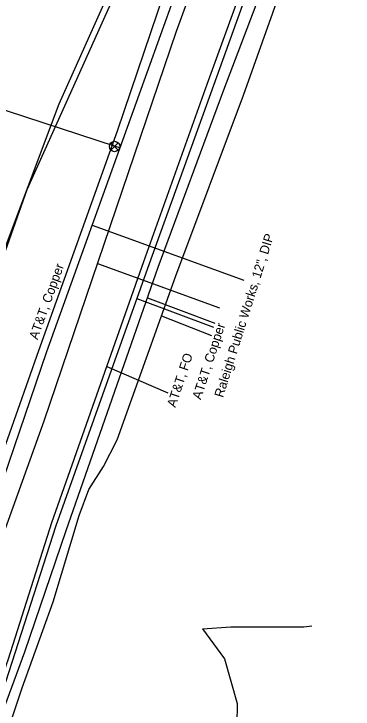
# Model space of a CAD drawing. Extents: x 2070721 to 2083039, y 729290 to 737883.
# Drawn here: x 2081041.1 to 2081187.2, y 732953.4 to 733253 of the extents above; entities that cross this region are included whole.
import ezdxf

# ---------------------------------------------------------------- set-up
doc = ezdxf.new("R2010")
doc.units = 0
for name, color, linetype in [('COGO Default Point Elevation', 7, 'Continuous'), ('Exist Utilities Gas UG Line SUE Cogo Point CELL', 7, 'Continuous'), ('Exist Utilities Gas UG Line SUE LOS B Cogo Comment', 7, 'Continuous'), ('Exist Utilities Gas Valve Cogo Elevation', 7, 'Continuous'), ('Exist Utilities TV Hand Hole CELL', 7, 'Continuous'), ('Exist Utilities TV Pedestal Cogo Elevation', 7, 'Continuous'), ('Exist Utilities TV Pedestal Cogo Number', 7, 'Continuous'), ('Exist Utilities TV UG Cable Cogo Point CELL', 7, 'Continuous'), ('Exist Utilities TV UG Cable SUE LOS C Cogo Comment', 7, 'Continuous'), ('Exist Utilities TV UG Cable SUE LOS C Cogo Point CELL', 7, 'Continuous'), ('Exist Utilities Water Manhole Cogo Elevation', 7, 'Continuous'), ('Exist Utilities Water Meter Cogo Number', 7, 'Continuous')]:
    doc.layers.add(name, color=color, linetype=linetype)

msp = doc.modelspace()

# ---------------------------------------------------------------- linework, layer by layer
at = {"layer": 'COGO Default Point Elevation'}
msp.add_lwpolyline([(2081086.05, 733197.43), (2081082.9, 733194.28), (2081084.47, 733195.86), (2081086.05, 733194.28), (2081082.9, 733197.43)], dxfattribs=at)
msp.add_circle((2081084.47, 733195.86), 2.23, dxfattribs=at)
at = {"layer": 'Exist Utilities Gas Valve Cogo Elevation'}
for p, q in [((2081077.1, 733145.5), (2081129.64, 733126.3)), ((2081094.04, 733130.35), (2081127.01, 733118.02)), ((2081098.66, 733130.6), (2081127.65, 733119.69)), ((2081104.65, 733122.9), (2081126.24, 733114.42))]:
    msp.add_line(p, q, dxfattribs=at)
at = {"layer": 'Exist Utilities TV Hand Hole CELL'}
msp.add_line((2081074.84, 733161.91), (2081140.08, 733138.21), dxfattribs=at)
at = {"layer": 'Exist Utilities TV Pedestal Cogo Elevation'}
for points in [[(2080968.02, 732853.09), (2080971.09, 732863.55), (2080973.36, 732870.49), (2081004.03, 732959.14), (2081024.87, 733018.36), (2081055.27, 733107.45), (2081086.77, 733195.01), (2081116.19, 733277.07), (2081135.71, 733336.57)], [(2081012.75, 733219.05), (2081038.17, 733211.25), (2081084.66, 733195.95), (2081086.52, 733195.46)]]:
    msp.add_lwpolyline(points, dxfattribs=at)
at = {"layer": 'Exist Utilities TV Pedestal Cogo Number'}
msp.add_lwpolyline([(2080924.17, 732884.04), (2080930.33, 732882.17), (2080949.02, 732923.62), (2080986.84, 733002.49), (2081018.88, 733098.52), (2081046.79, 733177.28), (2081082.41, 733256.43), (2081124.09, 733353.56), (2081157.6, 733423.49)], dxfattribs=at)
at = {"layer": 'Exist Utilities TV UG Cable Cogo Point CELL'}
for points in [[(2080953.21, 732796.69), (2081054.09, 733077.62), (2081111.09, 733245.57), (2081176.08, 733423.78), (2081231.97, 733580.28), (2081320.16, 733847.08), (2081418.84, 734093.09), (2081467.34, 734224.03), (2081494.06, 734287.2), (2081526.74, 734352.01), (2081556, 734404.62), (2081808.13, 734757.73), (2081845.73, 734804.26), (2081874.67, 734821.58), (2081898.66, 734810.94), (2081917.15, 734795.51)], [(2080971.45, 732791.05), (2081028.93, 732955.93), (2081037.58, 732965.12), (2081059.34, 733032.5), (2081099.5, 733145.5), (2081127.24, 733222.27), (2081165.53, 733329.08), (2081197.08, 733415.76), (2081225.51, 733493.81), (2081252.34, 733568.18), (2081252.65, 733568.73)], [(2080977.85, 732787.5), (2081009.55, 732879.6), (2081045.87, 732978.13), (2081063.56, 733030.35), (2081103.18, 733143.81), (2081131.57, 733220.23), (2081172.06, 733327.38), (2081203.1, 733413.05), (2081232.13, 733491.49), (2081257.07, 733565.11), (2081257.51, 733566.68)], [(2080980.31, 732787.04), (2081017.13, 732880.26), (2081044.65, 732962.53), (2081058.02, 732999.54), (2081069.26, 733036.84), (2081073.31, 733048.09), (2081079.75, 733057.99), (2081085.51, 733069.49), (2081110.84, 733140.06), (2081139.9, 733217.95), (2081177.19, 733322.59), (2081208.97, 733410.75), (2081237.5, 733489.4), (2081264.77, 733561.01)], [(2080944.31, 732798.44), (2080951.65, 732814.71), (2080971.81, 732874.01), (2081001.7, 732960.05), (2081020.52, 733019.4), (2081051.78, 733107.87), (2081085.75, 733202.6), (2081111.57, 733279.04), (2081128.94, 733334.77), (2081148.26, 733379.04), (2081175.1, 733448.52), (2081180.53, 733478.86)]]:
    msp.add_lwpolyline(points, dxfattribs=at)
at = {"layer": 'Exist Utilities TV UG Cable SUE LOS C Cogo Comment'}
for points in [[(2081122.3, 732987.96), (2081134.51, 732988.79), (2081149.63, 732988.79), (2081165.98, 732988.79), (2081169.37, 732989.33)], [(2081122.3, 732987.96), (2081131.78, 732974.98), (2081137.18, 732955.83), (2081136.91, 732937.96)]]:
    msp.add_lwpolyline(points, dxfattribs=at)
at = {"layer": 'Exist Utilities TV UG Cable SUE LOS C Cogo Point CELL'}
for points in [[(2081060.57, 733214.24), (2081129.62, 733368.62), (2081142.99, 733409.6), (2081173.13, 733492.79), (2081185.02, 733525.68), (2081211.4, 733608.97), (2081237.57, 733665.91), (2081235.81, 733672.2)], [(2080974.54, 732788.58), (2081004.48, 732877.32), (2081038.77, 732975.1), (2081057.5, 733033.86), (2081097.09, 733146.25), (2081124.3, 733222.73), (2081163.35, 733330.31), (2081194.31, 733416.96), (2081222.79, 733494.92), (2081247.13, 733564.12), (2081248.81, 733567.64)], [(2080978.07, 733014.44), (2080998.67, 733069.39), (2081018.84, 733124), (2081033.47, 733142.22), (2081060.57, 733214.24)]]:
    msp.add_lwpolyline(points, dxfattribs=at)
at = {"layer": 'Exist Utilities Water Manhole Cogo Elevation'}
msp.add_line((2081081.16, 733101.05), (2081107.43, 733089.72), dxfattribs=at)

# ---------------------------------------------------------------- texts
at = {"layer": 'Exist Utilities Gas UG Line SUE Cogo Point CELL'}
msp.add_text('Raleigh Public Works, 12", DIP ', height=4, rotation=72.5496, dxfattribs=at).set_placement((2081131.1, 733087.38))
at = {"layer": 'Exist Utilities Gas UG Line SUE LOS B Cogo Comment'}
msp.add_text('AT&T, FO', height=4, rotation=71.7158, dxfattribs=at).set_placement((2081110.66, 733083.14))
at = {"layer": 'Exist Utilities Water Meter Cogo Number'}
for rotation, p in [(70.2708, (2081051.26, 733112.34)), (71.9145, (2081121.57, 733086.51))]:
    msp.add_text('AT&T, Copper', height=4, rotation=rotation, dxfattribs=at).set_placement(p)

doc.saveas('drawing.dxf')
